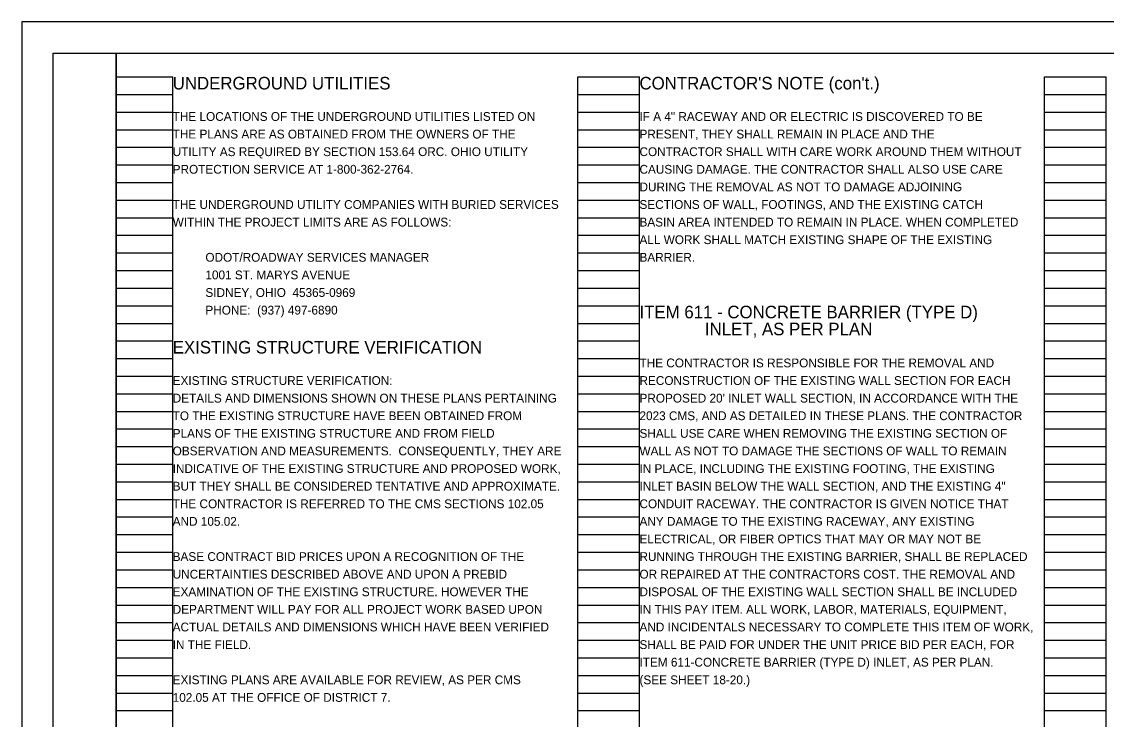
# Model space of a CAD drawing. Extents: x -18.2 to 34, y 0 to 22.
# Drawn here: x 0 to 17.24, y 10.9 to 22 of the extents above; entities that cross this region are included whole.
import ezdxf

# ---------------------------------------------------------------- set-up
doc = ezdxf.new("R2010")
doc.units = 0
for name, color, linetype in [('Default', 7, 'Continuous'), ('SH_Border', 7, 'Continuous'), ('SH_Cut_Line', 7, 'Continuous'), ('SH_Data', 7, 'Continuous'), ('SH_Text', 7, 'Continuous')]:
    doc.layers.add(name, color=color, linetype=linetype)

msp = doc.modelspace()

# ---------------------------------------------------------------- linework, layer by layer
at = {"layer": 'SH_Border'}
for points in [[(0.5, 21.5), (1.5, 21.5), (1.5, 0.5), (0.5, 0.5)], [(1.5, 21.5), (33.5, 21.5), (33.5, 0.5), (1.5, 0.5)]]:
    msp.add_lwpolyline(points, close=True, dxfattribs=at)
at = {"layer": 'SH_Cut_Line'}
msp.add_lwpolyline([(0, 0), (34, 0), (34, 22), (0, 22)], close=True, dxfattribs=at)
at = {"layer": 'SH_Data'}
for p, q in [((1.5, 0.962), (1.5, 21.122)), ((1.5, 21.122), (2.4, 21.122)), ((2.4, 0.962), (2.4, 21.122)), ((8.84, 0.962), (8.84, 21.122)), ((8.84, 21.122), (9.82, 21.122)), ((9.82, 0.962), (9.82, 21.122)), ((16.26, 0.962), (16.26, 21.122)), ((16.26, 21.122), (17.24, 21.122)), ((17.24, 0.962), (17.24, 21.122)), ((1.5, 20.842), (2.4, 20.842)), ((8.84, 20.842), (9.82, 20.842)), ((16.26, 20.842), (17.24, 20.842)), ((1.5, 20.562), (2.4, 20.562)), ((8.84, 20.562), (9.82, 20.562)), ((16.26, 20.562), (17.24, 20.562)), ((1.5, 20.282), (2.4, 20.282)), ((8.84, 20.282), (9.82, 20.282)), ((16.26, 20.282), (17.24, 20.282)), ((1.5, 20.002), (2.4, 20.002)), ((8.84, 20.002), (9.82, 20.002)), ((16.26, 20.002), (17.24, 20.002)), ((1.5, 19.722), (2.4, 19.722)), ((8.84, 19.722), (9.82, 19.722)), ((16.26, 19.722), (17.24, 19.722)), ((1.5, 19.442), (2.4, 19.442)), ((8.84, 19.442), (9.82, 19.442)), ((16.26, 19.442), (17.24, 19.442)), ((1.5, 19.162), (2.4, 19.162)), ((8.84, 19.162), (9.82, 19.162)), ((16.26, 19.162), (17.24, 19.162)), ((1.5, 18.882), (2.4, 18.882)), ((8.84, 18.882), (9.82, 18.882)), ((16.26, 18.882), (17.24, 18.882)), ((1.5, 18.602), (2.4, 18.602)), ((8.84, 18.602), (9.82, 18.602)), ((16.26, 18.602), (17.24, 18.602)), ((1.5, 18.322), (2.4, 18.322)), ((8.84, 18.322), (9.82, 18.322)), ((16.26, 18.322), (17.24, 18.322)), ((1.5, 18.042), (2.4, 18.042)), ((8.84, 18.042), (9.82, 18.042)), ((16.26, 18.042), (17.24, 18.042)), ((1.5, 17.762), (2.4, 17.762)), ((8.84, 17.762), (9.82, 17.762)), ((16.26, 17.762), (17.24, 17.762)), ((1.5, 17.482), (2.4, 17.482)), ((8.84, 17.482), (9.82, 17.482)), ((16.26, 17.482), (17.24, 17.482)), ((1.5, 17.202), (2.4, 17.202)), ((8.84, 17.202), (9.82, 17.202)), ((16.26, 17.202), (17.24, 17.202)), ((1.5, 16.922), (2.4, 16.922)), ((8.84, 16.922), (9.82, 16.922)), ((16.26, 16.922), (17.24, 16.922)), ((1.5, 16.642), (2.4, 16.642)), ((8.84, 16.642), (9.82, 16.642)), ((16.26, 16.642), (17.24, 16.642)), ((1.5, 16.362), (2.4, 16.362)), ((8.84, 16.362), (9.82, 16.362)), ((16.26, 16.362), (17.24, 16.362)), ((1.5, 16.082), (2.4, 16.082)), ((8.84, 16.082), (9.82, 16.082)), ((16.26, 16.082), (17.24, 16.082)), ((1.5, 15.802), (2.4, 15.802)), ((8.84, 15.802), (9.82, 15.802)), ((16.26, 15.802), (17.24, 15.802)), ((1.5, 15.522), (2.4, 15.522)), ((8.84, 15.522), (9.82, 15.522)), ((16.26, 15.522), (17.24, 15.522)), ((1.5, 15.242), (2.4, 15.242)), ((8.84, 15.242), (9.82, 15.242)), ((16.26, 15.242), (17.24, 15.242)), ((1.5, 14.962), (2.4, 14.962)), ((8.84, 14.962), (9.82, 14.962)), ((16.26, 14.962), (17.24, 14.962)), ((1.5, 14.682), (2.4, 14.682)), ((8.84, 14.682), (9.82, 14.682)), ((16.26, 14.682), (17.24, 14.682)), ((1.5, 14.402), (2.4, 14.402)), ((8.84, 14.402), (9.82, 14.402)), ((16.26, 14.402), (17.24, 14.402)), ((1.5, 14.122), (2.4, 14.122)), ((8.84, 14.122), (9.82, 14.122)), ((16.26, 14.122), (17.24, 14.122)), ((1.5, 13.842), (2.4, 13.842)), ((8.84, 13.842), (9.82, 13.842)), ((16.26, 13.842), (17.24, 13.842)), ((1.5, 13.562), (2.4, 13.562)), ((8.84, 13.562), (9.82, 13.562)), ((16.26, 13.562), (17.24, 13.562)), ((1.5, 13.282), (2.4, 13.282)), ((8.84, 13.282), (9.82, 13.282)), ((16.26, 13.282), (17.24, 13.282)), ((1.5, 13.002), (2.4, 13.002)), ((8.84, 13.002), (9.82, 13.002)), ((16.26, 13.002), (17.24, 13.002)), ((1.5, 12.722), (2.4, 12.722)), ((8.84, 12.722), (9.82, 12.722)), ((16.26, 12.722), (17.24, 12.722)), ((1.5, 12.442), (2.4, 12.442)), ((8.84, 12.442), (9.82, 12.442)), ((16.26, 12.442), (17.24, 12.442)), ((1.5, 12.162), (2.4, 12.162)), ((8.84, 12.162), (9.82, 12.162)), ((16.26, 12.162), (17.24, 12.162)), ((1.5, 11.882), (2.4, 11.882)), ((8.84, 11.882), (9.82, 11.882)), ((16.26, 11.882), (17.24, 11.882)), ((1.5, 11.602), (2.4, 11.602)), ((8.84, 11.602), (9.82, 11.602)), ((16.26, 11.602), (17.24, 11.602)), ((1.5, 11.322), (2.4, 11.322)), ((8.84, 11.322), (9.82, 11.322)), ((16.26, 11.322), (17.24, 11.322)), ((1.5, 11.042), (2.4, 11.042)), ((8.84, 11.042), (9.82, 11.042)), ((16.26, 11.042), (17.24, 11.042))]:
    msp.add_line(p, q, dxfattribs=at)

# ---------------------------------------------------------------- texts
at = {"layer": 'Default'}
for s, p in [('UNDERGROUND UTILITIES', (2.4, 20.922)), ("CONTRACTOR'S NOTE (con't.)", (9.82, 20.922)), ('ITEM 611 - CONCRETE BARRIER (TYPE D) ', (9.82, 17.282)), ('              INLET, AS PER PLAN', (9.82, 17.012)), ('EXISTING STRUCTURE VERIFICATION', (2.4, 16.722))]:
    msp.add_text(s, height=0.2, dxfattribs=at).set_placement(p)
at = {"layer": 'SH_Text'}
for s, p in [('THE LOCATIONS OF THE UNDERGROUND UTILITIES LISTED ON ', (2.4, 20.422)), ('IF A 4" RACEWAY AND OR ELECTRIC IS DISCOVERED TO BE ', (9.82, 20.422)), ('THE PLANS ARE AS OBTAINED FROM THE OWNERS OF THE ', (2.4, 20.142)), ('PRESENT, THEY SHALL REMAIN IN PLACE AND THE ', (9.82, 20.142)), ('UTILITY AS REQUIRED BY SECTION 153.64 ORC. OHIO UTILITY ', (2.4, 19.862)), ('CONTRACTOR SHALL WITH CARE WORK AROUND THEM WITHOUT ', (9.82, 19.862)), ('PROTECTION SERVICE AT 1-800-362-2764.', (2.4, 19.582)), ('CAUSING DAMAGE. THE CONTRACTOR SHALL ALSO USE CARE ', (9.82, 19.582)), ('DURING THE REMOVAL AS NOT TO DAMAGE ADJOINING ', (9.82, 19.302)), ('THE UNDERGROUND UTILITY COMPANIES WITH BURIED SERVICES ', (2.4, 19.022)), ('SECTIONS OF WALL, FOOTINGS, AND THE EXISTING CATCH ', (9.82, 19.022)), ('WITHIN THE PROJECT LIMITS ARE AS FOLLOWS:', (2.4, 18.742)), ('BASIN AREA INTENDED TO REMAIN IN PLACE. WHEN COMPLETED ', (9.82, 18.742)), ('ALL WORK SHALL MATCH EXISTING SHAPE OF THE EXISTING ', (9.82, 18.462)), ('          ODOT/ROADWAY SERVICES MANAGER', (2.4, 18.182)), ('BARRIER. ', (9.82, 18.182)), ('          1001 ST. MARYS AVENUE', (2.4, 17.902)), ('          SIDNEY, OHIO  45365-0969', (2.4, 17.622)), ('          PHONE:  (937) 497-6890', (2.4, 17.342)), ('THE CONTRACTOR IS RESPONSIBLE FOR THE REMOVAL AND ', (9.82, 16.502)), ('EXISTING STRUCTURE VERIFICATION:', (2.4, 16.222)), ('RECONSTRUCTION OF THE EXISTING WALL SECTION FOR EACH ', (9.82, 16.222)), ('DETAILS AND DIMENSIONS SHOWN ON THESE PLANS PERTAINING', (2.4, 15.942)), ("PROPOSED 20' INLET WALL SECTION, IN ACCORDANCE WITH THE ", (9.82, 15.942)), ('TO THE EXISTING STRUCTURE HAVE BEEN OBTAINED FROM ', (2.4, 15.662)), ('2023 CMS, AND AS DETAILED IN THESE PLANS. THE CONTRACTOR ', (9.82, 15.662)), ('PLANS OF THE EXISTING STRUCTURE AND FROM FIELD', (2.4, 15.382)), ('SHALL USE CARE WHEN REMOVING THE EXISTING SECTION OF ', (9.82, 15.382)), ('OBSERVATION AND MEASUREMENTS.  CONSEQUENTLY, THEY ARE', (2.4, 15.102)), ('WALL AS NOT TO DAMAGE THE SECTIONS OF WALL TO REMAIN ', (9.82, 15.102)), ('INDICATIVE OF THE EXISTING STRUCTURE AND PROPOSED WORK,', (2.4, 14.822)), ('IN PLACE, INCLUDING THE EXISTING FOOTING, THE EXISTING ', (9.82, 14.822)), ('BUT THEY SHALL BE CONSIDERED TENTATIVE AND APPROXIMATE.', (2.4, 14.542)), ('INLET BASIN BELOW THE WALL SECTION, AND THE EXISTING 4" ', (9.82, 14.542)), ('THE CONTRACTOR IS REFERRED TO THE CMS SECTIONS 102.05 ', (2.4, 14.262)), ('CONDUIT RACEWAY. THE CONTRACTOR IS GIVEN NOTICE THAT ', (9.82, 14.262)), ('AND 105.02.', (2.4, 13.982)), ('ANY DAMAGE TO THE EXISTING RACEWAY, ANY EXISTING ', (9.82, 13.982)), ('ELECTRICAL, OR FIBER OPTICS THAT MAY OR MAY NOT BE ', (9.82, 13.702)), ('BASE CONTRACT BID PRICES UPON A RECOGNITION OF THE', (2.4, 13.422)), ('RUNNING THROUGH THE EXISTING BARRIER, SHALL BE REPLACED ', (9.82, 13.422)), ('UNCERTAINTIES DESCRIBED ABOVE AND UPON A PREBID', (2.4, 13.142)), ('OR REPAIRED AT THE CONTRACTORS COST. THE REMOVAL AND ', (9.82, 13.142)), ('EXAMINATION OF THE EXISTING STRUCTURE. HOWEVER THE', (2.4, 12.862)), ('DISPOSAL OF THE EXISTING WALL SECTION SHALL BE INCLUDED ', (9.82, 12.862)), ('DEPARTMENT WILL PAY FOR ALL PROJECT WORK BASED UPON', (2.4, 12.582)), ('IN THIS PAY ITEM. ALL WORK, LABOR, MATERIALS, EQUIPMENT, ', (9.82, 12.582)), ('ACTUAL DETAILS AND DIMENSIONS WHICH HAVE BEEN VERIFIED', (2.4, 12.302)), ('AND INCIDENTALS NECESSARY TO COMPLETE THIS ITEM OF WORK, ', (9.82, 12.302)), ('IN THE FIELD.', (2.4, 12.022)), ('SHALL BE PAID FOR UNDER THE UNIT PRICE BID PER EACH, FOR ', (9.82, 12.022)), ('ITEM 611-CONCRETE BARRIER (TYPE D) INLET, AS PER PLAN. ', (9.82, 11.742)), ('EXISTING PLANS ARE AVAILABLE FOR REVIEW, AS PER CMS ', (2.4, 11.462)), ('(SEE SHEET 18-20.)', (9.82, 11.462)), ('102.05 AT THE OFFICE OF DISTRICT 7.', (2.4, 11.182))]:
    msp.add_text(s, height=0.14, dxfattribs=at).set_placement(p)

doc.saveas('drawing.dxf')
